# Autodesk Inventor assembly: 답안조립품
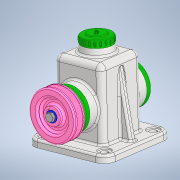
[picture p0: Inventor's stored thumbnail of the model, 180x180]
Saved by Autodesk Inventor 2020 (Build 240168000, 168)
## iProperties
Created: 2021-07
Part Number: 답안조립품
Document SubType Name: Assembly
Designer: Owner
Author: Owner
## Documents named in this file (14)
- C:\Users\Owner\Desktop\710715V1006\710715V1006\답안조립품.iam
- C:\Users\Owner\Desktop\710715V1006\710715V1006\본체.ipt
- C:\Users\Owner\Desktop\710715V1006\710715V1006\V-벨트풀리.ipt
- C:\Users\Owner\Desktop\710715V1006\710715V1006\뒤커버.ipt
- C:\Users\Owner\Desktop\710715V1006\710715V1006\멈춤링 15 x 1.ipt
- C:\Users\Owner\Desktop\710715V1006\710715V1006\베어링 15 x 35 x 11.ipt
- C:\Users\Owner\Desktop\710715V1006\710715V1006\볼트 M4 x 10.ipt
- C:\Users\Owner\Desktop\710715V1006\710715V1006\볼트 M6 x 12.ipt
- C:\Users\Owner\Desktop\710715V1006\710715V1006\상부캡.ipt
- C:\Users\Owner\Desktop\710715V1006\710715V1006\앞커버.ipt
- C:\Users\Owner\Desktop\710715V1006\710715V1006\오일실 15 25 7.ipt
- C:\Users\Owner\Desktop\710715V1006\710715V1006\와셔.ipt
- C:\Users\Owner\Desktop\710715V1006\710715V1006\축.ipt
- C:\Users\Owner\Desktop\710715V1006\710715V1006\키 5 x 5 x 14.ipt
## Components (1 placed, 1 different names)
1. V-벨트풀리:1
